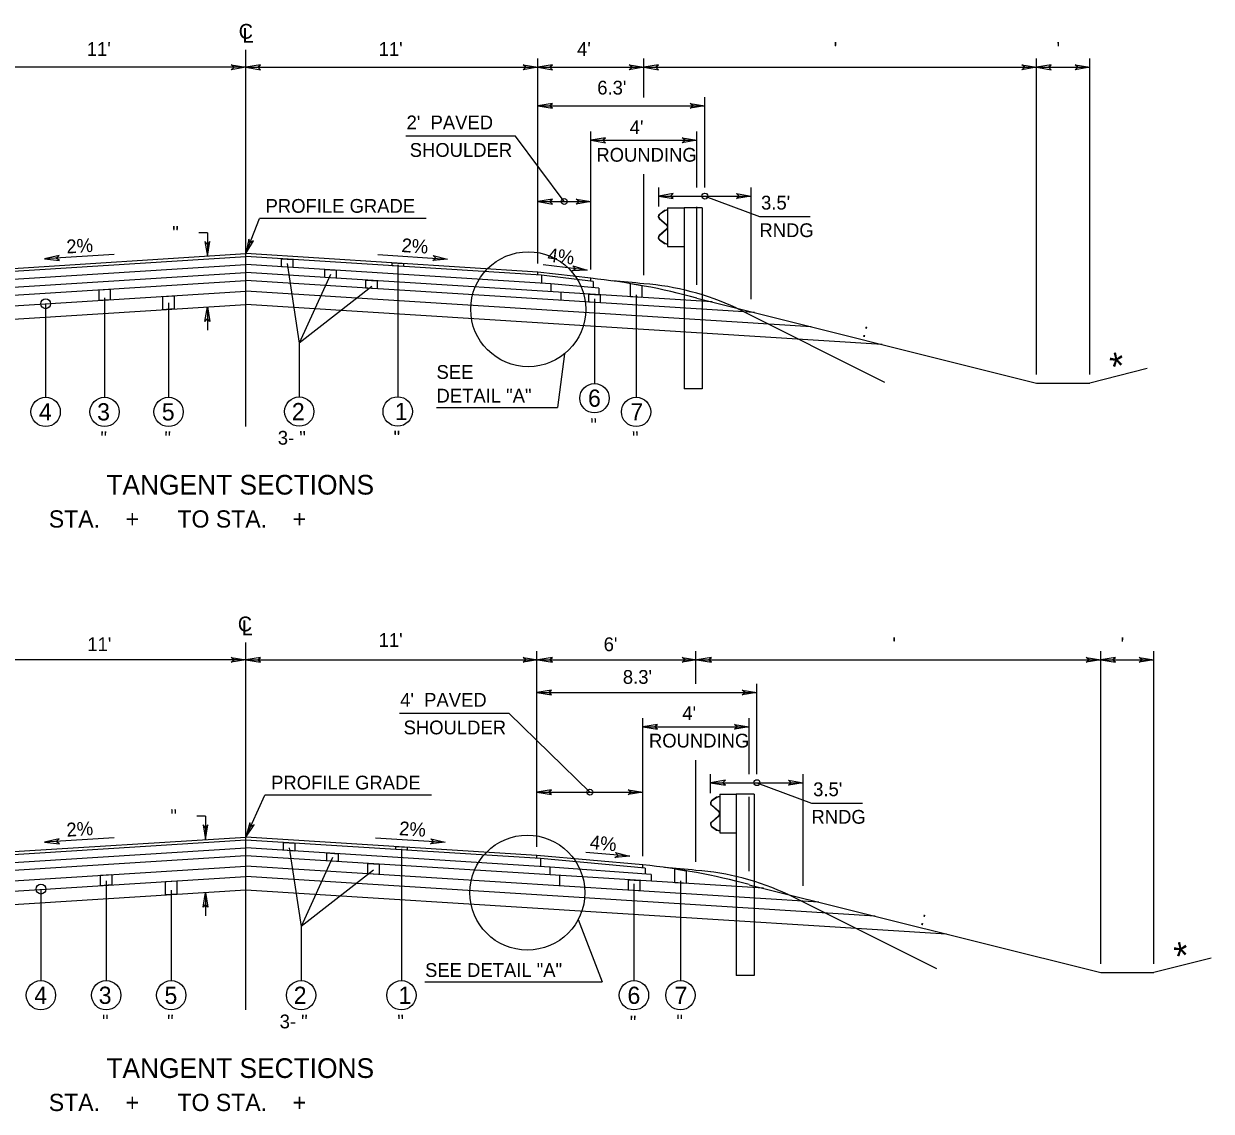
# Model space of a CAD drawing. Extents: x -592 to 1199, y -590 to 416.
# Drawn here: x -70.2 to 50.4, y -214.4 to -104 of the extents above; entities that cross this region are included whole.
import ezdxf

# ---------------------------------------------------------------- set-up
doc = ezdxf.new("R2010")
doc.units = 0
doc.layers.add('1', color=7, linetype='Continuous')
doc.layers.add('Des_ Drain_ Ftrs', color=7, linetype='Continuous')

msp = doc.modelspace()

# ---------------------------------------------------------------- linework, layer by layer
at = {"layer": '1'}
for p, q in [((-47.65, -144.86), (-47.65, -106.62)), ((-47.65, -108.38), (-77.29, -108.38)), ((-47.65, -108.38), (-18.02, -108.38)), ((-18.02, -128.3), (-18.02, -107.5)), ((-18.02, -108.38), (-7.24, -108.38)), ((-7.24, -111.45), (-7.24, -107.5)), ((-7.24, -108.38), (32.66, -108.38)), ((32.66, -139.57), (32.66, -107.5)), ((32.66, -108.38), (38.05, -108.38)), ((38.05, -139.57), (38.05, -107.5)), ((-1.04, -120.58), (-1.04, -111.42)), ((-18.02, -112.3), (-1.04, -112.3)), ((-20.29, -115.38), (-31.43, -115.38)), ((-15.32, -122.02), (-20.29, -115.38)), ((-12.63, -128.93), (-12.63, -114.91)), ((-12.63, -115.79), (-1.85, -115.79)), ((-1.85, -120.58), (-1.85, -114.91)), ((-7.24, -129.49), (-7.24, -119.22)), ((-5.73, -122.53), (-5.73, -120.58)), ((3.65, -131.94), (3.65, -120.58)), ((-5.73, -121.46), (3.65, -121.46)), ((-1.04, -121.46), (4.51, -123.53)), ((-18.02, -122.02), (-12.63, -122.02)), ((-5.14, -122.93), (-5.65, -123.32)), ((-5.12, -122.96), (-5.64, -123.34)), ((-4.82, -122.87), (-5.14, -122.93)), ((-4.82, -122.9), (-5.12, -122.96)), ((-4.82, -122.64), (-4.82, -126.57)), ((-4.82, -122.64), (-3.14, -122.64)), ((-3.14, -122.64), (-3.14, -141.04)), ((-1.31, -122.64), (-3.14, -122.64)), ((-1.85, -130.46), (-1.85, -122.56)), ((-1.31, -122.64), (-1.31, -141.04)), ((-47.65, -127.31), (-46.28, -123.74)), ((-29.36, -123.74), (-46.28, -123.74)), ((-5.67, -123.75), (-4.94, -124.38)), ((-5.65, -123.73), (-4.92, -124.36)), ((4.51, -123.53), (9.67, -123.53)), ((-51.57, -125.19), (-52.45, -125.19)), ((-51.57, -125.19), (-51.57, -127.56)), ((-4.94, -124.83), (-5.67, -125.47)), ((-4.92, -124.86), (-5.65, -125.49)), ((-4.85, -124.57), (-4.85, -124.65)), ((-4.82, -124.57), (-4.82, -124.65)), ((-5.65, -125.9), (-5.14, -126.29)), ((-5.64, -125.88), (-5.12, -126.26)), ((-5.14, -126.29), (-4.82, -126.35)), ((-5.12, -126.26), (-4.82, -126.32)), ((-4.82, -126.57), (-3.14, -126.57)), ((-77.65, -129.5), (-47.65, -127.61)), ((-77.29, -129.18), (-47.65, -127.31)), ((-61.04, -127.41), (-68.11, -127.85)), ((-18.02, -129.18), (-47.65, -127.31)), ((-17.65, -129.5), (-47.65, -127.61)), ((-34.25, -127.41), (-27.17, -127.86)), ((-78.64, -130.37), (-47.65, -128.42)), ((-16.67, -130.37), (-47.65, -128.42)), ((-43.48, -128.3), (-42.24, -136.4)), ((-32.24, -128.43), (-32.24, -141.86)), ((-13, -128.98), (-17.47, -128.45)), ((-99.32, -133.29), (-47.65, -130.04)), ((-95, -132.21), (-47.65, -129.23)), ((-0.31, -132.21), (-47.65, -129.23)), ((4.01, -133.29), (-47.65, -130.04)), ((-39.08, -129.42), (-42.24, -136.4)), ((-18.02, -129.48), (-18.02, -129.18)), ((-12.63, -129.81), (-18.02, -129.18)), ((-17.65, -129.5), (-17.65, -130.31)), ((-12.39, -130.14), (-17.65, -129.5)), ((-12.63, -130.11), (-12.63, -129.81)), ((-12.39, -130.14), (-12.39, -130.75)), ((-105.09, -134.73), (-47.65, -131.12)), ((9.77, -134.73), (-47.65, -131.12)), ((-34.88, -130.64), (-42.24, -136.4)), ((-16.67, -130.37), (-16.67, -131.18)), ((-11.8, -130.8), (-16.67, -130.37)), ((-15.68, -131.24), (-15.68, -132.05)), ((-11.8, -130.8), (-11.8, -131.48)), ((-5.73, -130.59), (-5.73, -130.59)), ((-112.3, -136.53), (-47.65, -132.47)), ((-68, -132.4), (-68, -141.89)), ((-62.01, -131.78), (-62.01, -141.89)), ((-55.51, -132.29), (-55.51, -141.89)), ((16.98, -136.53), (-47.65, -132.47)), ((-12.25, -131.91), (-12.25, -140.5)), ((-8.02, -131.5), (-8.02, -141.89)), ((-1.85, -131.82), (32.66, -140.45)), ((-51.57, -132.71), (-51.57, -135.08)), ((2.15, -132.82), (17.2, -140.35)), ((-42.24, -136.4), (-42.24, -141.87)), ((-15.29, -137.48), (-16.01, -142.93)), ((43.88, -138.99), (38.05, -140.45)), ((-1.31, -141.04), (-3.14, -141.04)), ((32.66, -140.45), (38.05, -140.45)), ((32.66, -140.45), (38.05, -140.45)), ((-28.31, -142.93), (-16.01, -142.93)), ((-47.65, -204.12), (-47.65, -166.8)), ((-47.65, -168.56), (-77.2, -168.56)), ((-47.65, -168.56), (-18.02, -168.56)), ((-18.11, -187.55), (-18.11, -167.68)), ((-18.02, -168.56), (-1.85, -168.56)), ((-1.94, -171), (-1.94, -167.68)), ((-1.85, -168.56), (39.18, -168.56)), ((39.18, -199.45), (39.18, -167.68)), ((39.18, -168.56), (44.57, -168.56)), ((44.57, -199.45), (44.57, -167.68)), ((4.25, -180.16), (4.25, -171)), ((-18.12, -171.88), (4.25, -171.88)), ((-20.91, -174.03), (-32.05, -174.03)), ((-12.72, -182), (-20.91, -174.03)), ((-7.33, -188.51), (-7.33, -174.49)), ((3.45, -180.16), (3.45, -174.49)), ((-7.33, -175.37), (3.45, -175.37)), ((-1.94, -189.07), (-1.94, -178.75)), ((-0.45, -182.11), (-0.45, -180.16)), ((8.94, -191.5), (8.94, -180.16)), ((-18.11, -182), (-7.33, -182)), ((-0.45, -181.04), (8.94, -181.04)), ((4.25, -181.04), (9.8, -183.11)), ((-47.65, -186.57), (-45.72, -182.32)), ((-28.8, -182.32), (-45.72, -182.32)), ((-0.38, -183.32), (0.35, -183.96)), ((0.15, -182.5), (-0.37, -182.89)), ((-0.36, -183.3), (0.37, -183.94)), ((0.16, -182.53), (-0.35, -182.92)), ((0.47, -182.45), (0.15, -182.5)), ((0.47, -182.48), (0.16, -182.53)), ((0.47, -182.22), (0.47, -186.15)), ((0.47, -182.22), (2.15, -182.22)), ((2.15, -182.22), (2.15, -200.62)), ((3.98, -182.22), (2.15, -182.22)), ((3.45, -190.04), (3.45, -182.47)), ((3.98, -182.22), (3.98, -200.62)), ((9.8, -183.11), (14.96, -183.11)), ((-51.76, -184.45), (-52.64, -184.45)), ((-51.76, -184.45), (-51.76, -186.82)), ((0.35, -184.41), (-0.38, -185.05)), ((0.37, -184.43), (-0.36, -185.07)), ((0.44, -184.15), (0.44, -184.22)), ((0.47, -184.15), (0.47, -184.22)), ((-0.37, -185.48), (0.15, -185.87)), ((-0.35, -185.45), (0.16, -185.84)), ((-77.65, -188.75), (-47.65, -186.86)), ((-77.29, -188.42), (-47.65, -186.56)), ((-61.03, -186.64), (-68.11, -187.09)), ((-18.11, -188.43), (-47.65, -186.57)), ((-17.74, -188.75), (-47.65, -186.87)), ((-34.5, -186.64), (-27.42, -187.08)), ((0.15, -185.87), (0.47, -185.92)), ((0.16, -185.84), (0.47, -185.89)), ((0.47, -186.15), (2.15, -186.15)), ((-78.62, -189.6), (-47.65, -187.66)), ((-16.77, -189.61), (-47.65, -187.67)), ((-43.27, -187.66), (-42.05, -195.66)), ((-31.86, -187.75), (-31.86, -201.15)), ((-8.66, -188.52), (-13.14, -188.12)), ((-100.33, -191.76), (-47.65, -188.45)), ((4.93, -191.77), (-47.65, -188.46)), ((-38.87, -188.65), (-42.05, -195.66)), ((-18.11, -188.73), (-18.11, -188.43)), ((-7.33, -189.39), (-18.11, -188.43)), ((-7.09, -189.71), (-17.74, -188.75)), ((-17.74, -188.75), (-17.74, -189.55)), ((-111.68, -194.6), (-47.65, -190.58)), ((-105.96, -193.17), (-47.65, -189.51)), ((10.54, -193.17), (-47.65, -189.51)), ((-34.7, -189.91), (-42.05, -195.66)), ((-16.77, -189.61), (-16.77, -190.41)), ((-6.51, -190.37), (-16.75, -189.62)), ((-15.79, -190.47), (-15.79, -191.52)), ((-7.33, -189.69), (-7.33, -189.39)), ((-7.09, -189.71), (-7.09, -190.32)), ((-6.51, -190.37), (-6.51, -191.04)), ((-0.45, -190.17), (-0.45, -190.17)), ((-61.85, -191.02), (-61.85, -201.15)), ((16.27, -194.6), (-47.65, -190.58)), ((-8.24, -191.3), (-8.24, -201.15)), ((-3.52, -191.02), (-3.52, -201.15)), ((3.45, -191.4), (39.18, -200.33)), ((-118.92, -196.41), (-47.65, -191.93)), ((-68.48, -191.85), (-68.48, -201.15)), ((-55.24, -191.94), (-55.24, -201.15)), ((-51.76, -192.19), (-51.76, -194.56)), ((23.5, -196.41), (-47.65, -191.94)), ((7.44, -192.4), (22.49, -199.92)), ((-13.9, -194.93), (-11.47, -201.27)), ((-42.05, -195.66), (-42.05, -201.15)), ((50.4, -198.88), (44.57, -200.33)), ((-29.47, -201.27), (-11.47, -201.27)), ((3.98, -200.62), (2.15, -200.62)), ((39.18, -200.33), (44.57, -200.33))]:
    msp.add_line(p, q, dxfattribs=at)
for points in [[(-44.05, -127.84), (-42.9, -127.91), (-42.9, -128.72), (-44.05, -128.65)], [(-39.65, -128.93), (-38.5, -129), (-38.5, -129.81), (-39.65, -129.73)], [(-32.81, -128.25), (-31.66, -128.32), (-31.66, -128.62), (-32.81, -128.55)], [(-35.46, -130), (-34.31, -130.07), (-34.31, -130.88), (-35.46, -130.81)], [(-62.58, -130.98), (-61.44, -130.91), (-61.44, -131.99), (-62.58, -132.06)], [(-12.82, -131.42), (-11.67, -131.49), (-11.67, -132.3), (-12.82, -132.23)], [(-8.59, -130.35), (-7.45, -130.55), (-7.45, -131.76), (-8.59, -131.69)], [(-56.08, -131.65), (-54.94, -131.58), (-54.94, -132.93), (-56.08, -133)], [(-43.84, -187.11), (-42.7, -187.18), (-42.7, -187.98), (-43.84, -187.91)], [(-32.43, -187.53), (-31.28, -187.6), (-31.28, -187.9), (-32.43, -187.83)], [(-39.44, -188.18), (-38.3, -188.25), (-38.3, -189.05), (-39.44, -188.98)], [(-35.27, -189.24), (-34.13, -189.31), (-34.13, -190.36), (-35.27, -190.29)], [(-62.42, -190.43), (-61.28, -190.36), (-61.28, -191.43), (-62.42, -191.5)], [(-4.1, -189.8), (-2.95, -189.99), (-2.95, -191.27), (-4.1, -191.2)], [(-55.81, -191.09), (-54.66, -191.02), (-54.66, -192.37), (-55.81, -192.44)], [(-8.81, -190.91), (-7.66, -190.98), (-7.66, -192.03), (-8.81, -191.96)]]:
    msp.add_lwpolyline(points, close=True, dxfattribs=at)
for centre, radius in [((-15.32, -122.02), 0.3), ((-1.04, -121.46), 0.3), ((-18.98, -132.96), 5.84), ((-68, -132.4), 0.5), ((-12.25, -141.99), 1.49), ((-68, -143.38), 1.49), ((-62.01, -143.38), 1.49), ((-55.51, -143.38), 1.49), ((-42.24, -143.35), 1.49), ((-32.24, -143.34), 1.49), ((-8.02, -143.38), 1.49), ((4.25, -181.04), 0.3), ((-12.72, -182), 0.3), ((-19.07, -192.21), 5.84), ((-68.48, -191.85), 0.5), ((-68.48, -202.63), 1.49), ((-61.85, -202.63), 1.49), ((-55.24, -202.63), 1.49), ((-42.05, -202.63), 1.49), ((-31.86, -202.63), 1.49), ((-8.24, -202.63), 1.49), ((-3.52, -202.63), 1.49)]:
    msp.add_circle(centre, radius, dxfattribs=at)
for centre, radius, start, end in [((-5.49, -123.54), 0.278, 126.9799, 229.021), ((-5.49, -123.54), 0.249, 126.9799, 229.021), ((-5.1, -124.57), 0.249, 0, 49.0365), ((-5.1, -124.65), 0.249, 310.9635, 0), ((-5.1, -124.57), 0.278, 0, 49.0365), ((-5.1, -124.65), 0.278, 310.9635, 0), ((-5.49, -125.68), 0.278, 130.979, 233.0201), ((-5.49, -125.68), 0.249, 130.979, 233.0201), ((-19.51, -196.65), 67.19, 74.7593, 84.1179), ((-18.06, -231.03), 101.24, 83.8633, 85.6775), ((-9.36, -157.65), 27.37, 65.1374, 85.5513), ((-0.2, -183.11), 0.278, 126.9799, 229.021), ((-0.2, -183.11), 0.249, 126.9799, 229.021), ((0.19, -184.15), 0.249, 0, 49.0365), ((0.19, -184.22), 0.249, 310.9635, 0), ((0.19, -184.15), 0.278, 0, 49.0365), ((0.19, -184.22), 0.278, 310.9635, 0), ((-0.2, -185.26), 0.278, 130.979, 233.0201), ((-0.2, -185.26), 0.249, 130.979, 233.0201), ((-14.21, -256.22), 67.19, 74.7611, 84.1196), ((-12.77, -290.61), 101.24, 83.8633, 85.6775), ((-4.07, -217.23), 27.37, 65.1374, 85.5513)]:
    msp.add_arc(centre, radius, start, end, dxfattribs=at)
at = {"layer": 'Des_ Drain_ Ftrs'}
for points in [[(-47.65, -108.38), (-49.14, -108.63), (-48.85, -108.38), (-49.14, -108.13)], [(-47.65, -108.38), (-46.16, -108.63), (-46.46, -108.38), (-46.16, -108.13)], [(-18.02, -108.38), (-19.51, -108.63), (-19.21, -108.38), (-19.51, -108.13)], [(-18.02, -108.38), (-16.53, -108.63), (-16.82, -108.38), (-16.53, -108.13)], [(-7.24, -108.38), (-8.73, -108.63), (-8.43, -108.38), (-8.73, -108.13)], [(-7.24, -108.38), (-5.75, -108.63), (-6.05, -108.38), (-5.75, -108.13)], [(32.66, -108.38), (31.17, -108.63), (31.47, -108.38), (31.17, -108.13)], [(32.66, -108.38), (34.15, -108.63), (33.86, -108.38), (34.15, -108.13)], [(38.05, -108.38), (36.56, -108.63), (36.86, -108.38), (36.56, -108.13)], [(-18.02, -112.3), (-16.53, -112.55), (-16.82, -112.3), (-16.53, -112.05)], [(-1.04, -112.3), (-2.53, -112.55), (-2.24, -112.3), (-2.53, -112.05)], [(-12.63, -115.79), (-11.14, -116.04), (-11.44, -115.79), (-11.14, -115.54)], [(-1.85, -115.79), (-3.34, -116.04), (-3.05, -115.79), (-3.34, -115.54)], [(-18.02, -122.02), (-16.53, -122.27), (-16.82, -122.02), (-16.53, -121.77)], [(-12.63, -122.02), (-14.12, -122.27), (-13.82, -122.02), (-14.12, -121.77)], [(-5.73, -121.46), (-4.25, -121.71), (-4.54, -121.46), (-4.25, -121.21)], [(3.65, -121.46), (2.16, -121.71), (2.46, -121.46), (2.16, -121.21)], [(-51.57, -127.56), (-51.32, -126.07), (-51.57, -126.37), (-51.82, -126.07)], [(-47.65, -127.31), (-46.89, -126.01), (-47.23, -126.2), (-47.35, -125.84)], [(-68.11, -127.85), (-66.61, -128.01), (-66.92, -127.78), (-66.64, -127.51)], [(-27.17, -127.86), (-28.68, -128.01), (-28.37, -127.78), (-28.64, -127.51)], [(-13, -128.98), (-14.51, -129.05), (-14.19, -128.84), (-14.45, -128.56)], [(-51.57, -132.71), (-51.32, -134.2), (-51.57, -133.91), (-51.82, -134.2)], [(-47.65, -168.56), (-49.14, -168.81), (-48.85, -168.56), (-49.14, -168.31)], [(-47.65, -168.56), (-46.16, -168.81), (-46.46, -168.56), (-46.16, -168.31)], [(-18.02, -168.56), (-19.5, -168.81), (-19.21, -168.56), (-19.5, -168.31)], [(-18.02, -168.56), (-16.53, -168.81), (-16.82, -168.56), (-16.53, -168.31)], [(-1.85, -168.56), (-3.34, -168.81), (-3.04, -168.56), (-3.34, -168.31)], [(-1.85, -168.56), (-0.36, -168.81), (-0.66, -168.56), (-0.36, -168.31)], [(39.18, -168.56), (37.69, -168.81), (37.99, -168.56), (37.69, -168.31)], [(39.18, -168.56), (40.67, -168.81), (40.37, -168.56), (40.67, -168.31)], [(44.57, -168.56), (43.08, -168.81), (43.38, -168.56), (43.08, -168.31)], [(-18.12, -171.88), (-16.63, -172.13), (-16.92, -171.88), (-16.63, -171.63)], [(4.25, -171.88), (2.76, -172.13), (3.05, -171.88), (2.76, -171.63)], [(-7.33, -175.37), (-5.84, -175.62), (-6.14, -175.37), (-5.84, -175.12)], [(3.45, -175.37), (1.96, -175.62), (2.25, -175.37), (1.96, -175.12)], [(-0.45, -181.04), (1.04, -181.28), (0.75, -181.04), (1.04, -180.79)], [(8.94, -181.04), (7.45, -181.28), (7.74, -181.04), (7.45, -180.79)], [(-18.11, -182), (-16.62, -182.24), (-16.91, -182), (-16.62, -181.75)], [(-7.33, -182), (-8.82, -182.24), (-8.52, -182), (-8.82, -181.75)], [(-51.76, -186.82), (-51.51, -185.33), (-51.76, -185.63), (-52, -185.33)], [(-47.65, -186.57), (-46.81, -185.32), (-47.16, -185.49), (-47.26, -185.12)], [(-68.11, -187.09), (-66.61, -187.24), (-66.92, -187.01), (-66.64, -186.75)], [(-27.42, -187.08), (-28.92, -187.24), (-28.61, -187.01), (-28.89, -186.74)], [(-8.66, -188.52), (-10.17, -188.64), (-9.85, -188.42), (-10.12, -188.14)], [(-51.76, -192.19), (-51.51, -193.68), (-51.76, -193.38), (-52.01, -193.68)]]:
    msp.add_lwpolyline(points, close=True, dxfattribs=at)

# ---------------------------------------------------------------- texts
at = {"layer": '1'}
for s, height, p in [("11'", 1.4, (-63.82, -107.23)), ("11'", 1.4, (-34.18, -107.23)), ("4'", 1.4, (-14.02, -107.23)), ("  '", 1.4, (11.01, -107.23)), (" '", 1.4, (34.16, -107.23)), ("6.3'", 1.4, (-11.97, -111.15)), ("2'  PAVED", 1.4, (-31.34, -114.68)), ("4'", 1.4, (-8.67, -115.17)), ('SHOULDER', 1.4, (-31.02, -117.48)), ('ROUNDING', 1.4, (-12.06, -117.97)), ('PROFILE GRADE', 1.4, (-45.66, -123.16)), ("3.5'", 1.4, (4.67, -122.83)), ('RNDG', 1.4, (4.5, -125.63)), ('SEE', 1.4, (-28.3, -140.03)), ('DETAIL "A"', 1.4, (-28.3, -142.43)), ('6', 1.75, (-12.91, -142.86)), ('4', 1.75, (-68.68, -144.25)), ('3', 1.75, (-62.77, -144.25)), ('5', 1.75, (-56.2, -144.25)), ('2', 1.75, (-42.99, -144.23)), ('1', 1.75, (-32.54, -144.22)), ('7', 1.75, (-8.61, -144.25)), (' "', 1.4, (-13.19, -145.44)), (' "', 1.4, (-62.95, -146.74)), (' "', 1.4, (-56.45, -146.74)), ('3- "', 1.4, (-44.42, -146.71)), (' "', 1.4, (-33.18, -146.7)), (' "', 1.4, (-8.96, -146.74)), ('TANGENT SECTIONS', 2, (-61.83, -151.78)), ('STA.    +      TO STA.    +     ', 1.75, (-67.68, -155.13)), ("11'", 1.4, (-63.77, -167.68)), ("11'", 1.4, (-34.18, -167.25)), ("6'", 1.4, (-11.32, -167.68)), ("  '", 1.4, (16.97, -167.68)), (" '", 1.4, (40.68, -167.68)), ("8.3'", 1.4, (-9.37, -171)), ("4'  PAVED", 1.4, (-31.99, -173.33)), ("4'", 1.4, (-3.33, -174.67)), ('SHOULDER', 1.4, (-31.64, -176.13)), ('ROUNDING', 1.4, (-6.72, -177.47)), ('PROFILE GRADE', 1.4, (-45.1, -181.73)), ("3.5'", 1.4, (9.96, -182.41)), ('RNDG', 1.4, (9.79, -185.21)), ('SEE DETAIL "A"', 1.4, (-29.46, -200.77)), ('4', 1.75, (-69.15, -203.51)), ('3', 1.75, (-62.61, -203.51)), ('5', 1.75, (-55.93, -203.51)), ('2', 1.75, (-42.8, -203.51)), ('1', 1.75, (-32.16, -203.51)), ('6', 1.75, (-8.9, -203.51)), ('7', 1.75, (-4.11, -203.51)), (' "', 1.4, (-62.79, -205.99)), (' "', 1.4, (-56.18, -205.99)), ('3- "', 1.4, (-44.23, -205.99)), (' "', 1.4, (-32.8, -205.99)), (' "', 1.4, (-9.18, -206.09)), ('  "', 1.4, (-4.97, -205.99)), ('TANGENT SECTIONS', 2, (-61.83, -211.03)), ('STA.    +      TO STA.    +     ', 1.75, (-67.68, -214.39))]:
    msp.add_text(s, height=height, dxfattribs=at).set_placement(p)
for s, height, rotation, p in [('  "', 1.4, 0.1438, (-56.18, -125.9)), ('2%', 1.4, 3.7203, (-65.85, -127.3)), ('2%', 1.4, 356.2797, (-31.89, -127.14)), ('4%', 1.4, 352.9919, (-17.08, -128.1)), (' : ', 1.4, 345.7718, (14.36, -135.58)), ('*', 2.8, 12.8479, (40.51, -140.26)), ('  "', 1.4, 0.1438, (-56.37, -185.16)), ('2%', 1.4, 3.723, (-65.84, -186.53)), ('2%', 1.4, 356.2769, (-32.13, -186.36)), ('4%', 1.4, 354.6097, (-12.77, -187.76)), (' : ', 1.4, 345.7718, (20.26, -195.31)), ('*', 2.8, 12.8479, (47.03, -200.14))]:
    msp.add_text(s, height=height, rotation=rotation, dxfattribs=at).set_placement(p)
at = {"layer": 'Des_ Drain_ Ftrs'}
for s, p in [('C', (-48.39, -105.48)), ('L', (-48, -105.88)), ('C', (-48.48, -165.67)), ('L', (-48.08, -166.06))]:
    msp.add_text(s, height=1.5, dxfattribs=at).set_placement(p)

doc.saveas('drawing.dxf')
